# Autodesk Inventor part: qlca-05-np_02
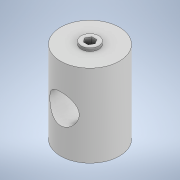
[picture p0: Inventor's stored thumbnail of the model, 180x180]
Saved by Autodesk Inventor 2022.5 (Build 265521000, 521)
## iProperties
Created: 2023-06
Part Number: qlca-05-np_02
Material: Generic
Document SubType Name: Modeling
Designer: ImaoCorp
Density: 1 g/cm^3
Appearance: Default
Author: ImaoCorp
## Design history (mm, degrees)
feature "qlca-05-np_02"
node "ソリッド1"
